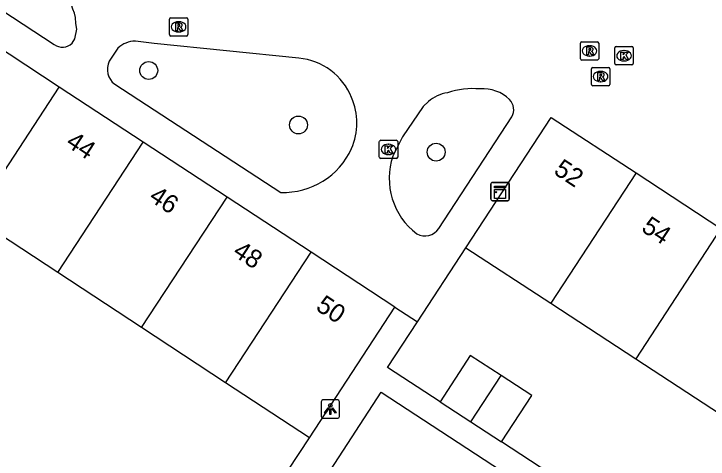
# Model space of a CAD drawing. Extents: x 159280 to 160375, y 384531 to 385872.
# Drawn here: x 159696.06 to 159733.94, y 384954.59 to 384978.88 of the extents above; entities that cross this region are included whole.
import ezdxf

# ---------------------------------------------------------------- set-up
doc = ezdxf.new("R2010")
doc.units = 0
for name, color, linetype in [('IMGEO_Boom', 7, 'Continuous'), ('IMGEO_Kast', 7, 'Continuous'), ('IMGEO_Kolk', 7, 'Continuous'), ('IMGEO_Lichtpunt', 7, 'Continuous'), ('IMGEO_Pand', 7, 'Continuous'), ('IMGEO_Pand_nummerreeks', 7, 'Continuous'), ('IMGEO_Rijbaan_lokaal_open', 7, 'Continuous'), ('IMGEO_Rioolput', 7, 'Continuous'), ('IMGEO_Voetpad_open', 7, 'Continuous')]:
    doc.layers.add(name, color=color, linetype=linetype)

msp = doc.modelspace()

# ---------------------------------------------------------------- linework, layer by layer
at = {"layer": 'IMGEO_Boom'}
for centre in [(159703.416, 384975.788), (159711.587, 384972.816), (159719.098, 384971.334)]:
    msp.add_circle(centre, 0.489, dxfattribs=at)
at = {"layer": 'IMGEO_Kast'}
for p, q in [((159722.091, 384968.761), (159722.091, 384969.602)), ((159722.091, 384969.602), (159722.091, 384968.761)), ((159722.166, 384969.686), (159723.007, 384969.686)), ((159723.007, 384969.686), (159722.166, 384969.686)), ((159723.091, 384969.611), (159723.091, 384968.77)), ((159723.091, 384968.77), (159723.091, 384969.611)), ((159723.016, 384968.686), (159722.175, 384968.686)), ((159722.175, 384968.686), (159723.016, 384968.686))]:
    msp.add_line(p, q, dxfattribs=at)
for points in [[(159722.286, 384969.476), (159722.886, 384969.476), (159722.886, 384969.391), (159722.286, 384969.391), (159722.286, 384969.476)], [(159722.286, 384969.301), (159722.886, 384969.301), (159722.886, 384968.812), (159722.286, 384968.812), (159722.286, 384969.301)]]:
    msp.add_lwpolyline(points, dxfattribs=at)
msp.add_circle((159722.37, 384969.15), 0.0377, dxfattribs=at)
for centre, start, end in [((159722.169, 384969.608), 92.4484, 184.2845), ((159722.169, 384969.608), 92.4484, 184.2845), ((159723.013, 384969.608), 2.4484, 94.2845), ((159723.013, 384969.608), 2.4484, 94.2845), ((159722.169, 384968.764), 182.4484, 274.2845), ((159722.169, 384968.764), 182.4484, 274.2845), ((159723.013, 384968.764), 272.4484, 4.2845), ((159723.013, 384968.764), 272.4484, 4.2845)]:
    msp.add_arc(centre, 0.0779, start, end, dxfattribs=at)
at = {"layer": 'IMGEO_Kolk'}
for p, q in [((159728.852, 384976.167), (159728.852, 384977.019)), ((159728.927, 384977.093), (159729.779, 384977.093)), ((159729.34, 384976.873), (159729.365, 384976.873)), ((159729.853, 384977.019), (159729.853, 384976.167)), ((159729.779, 384976.093), (159728.927, 384976.093)), ((159729.363, 384976.313), (159729.338, 384976.313)), ((159715.999, 384971.055), (159715.999, 384971.907)), ((159716.074, 384971.981), (159716.926, 384971.981)), ((159717, 384971.907), (159717, 384971.055)), ((159716.487, 384971.761), (159716.512, 384971.761)), ((159716.51, 384971.201), (159716.485, 384971.201)), ((159716.926, 384970.981), (159716.074, 384970.981))]:
    msp.add_line(p, q, dxfattribs=at)
for points in [[(159728.852, 384976.167), (159728.852, 384977.019)], [(159728.927, 384977.093), (159729.779, 384977.093)], [(159729.173, 384976.793), (159729.296, 384976.793), (159729.296, 384976.642), (159729.426, 384976.793), (159729.59, 384976.793), (159729.444, 384976.642), (159729.597, 384976.393), (159729.445, 384976.393), (159729.36, 384976.557), (159729.296, 384976.49), (159729.296, 384976.393), (159729.173, 384976.393), (159729.173, 384976.793)], [(159729.853, 384977.019), (159729.853, 384976.167)], [(159729.779, 384976.093), (159728.927, 384976.093)], [(159715.999, 384971.055), (159715.999, 384971.907)], [(159716.074, 384971.981), (159716.926, 384971.981)], [(159717, 384971.907), (159717, 384971.055)], [(159716.32, 384971.681), (159716.443, 384971.681), (159716.443, 384971.53), (159716.573, 384971.681), (159716.737, 384971.681), (159716.591, 384971.53), (159716.744, 384971.281), (159716.592, 384971.281), (159716.507, 384971.445), (159716.443, 384971.378), (159716.443, 384971.281), (159716.32, 384971.281), (159716.32, 384971.681)], [(159716.926, 384970.981), (159716.074, 384970.981)]]:
    msp.add_lwpolyline(points, dxfattribs=at)
for centre, start, end in [((159728.929, 384977.017), 91.552, 178.448), ((159728.929, 384977.017), 91.552, 178.448), ((159729.777, 384977.017), 1.552, 88.448), ((159729.777, 384977.017), 1.552, 88.448), ((159728.929, 384976.169), 181.552, 268.448), ((159728.929, 384976.169), 181.552, 268.448), ((159729.777, 384976.169), 271.552, 358.448), ((159729.777, 384976.169), 271.552, 358.448), ((159716.076, 384971.905), 91.552, 178.448), ((159716.076, 384971.905), 91.552, 178.448), ((159716.924, 384971.905), 1.552, 88.448), ((159716.924, 384971.905), 1.552, 88.448), ((159716.076, 384971.057), 181.552, 268.448), ((159716.076, 384971.057), 181.552, 268.448), ((159716.924, 384971.057), 271.552, 358.448), ((159716.924, 384971.057), 271.552, 358.448)]:
    msp.add_arc(centre, 0.0765, start, end, dxfattribs=at)
for centre, major_axis, ratio, start_param, end_param in [((159729.339, 384976.593), (-0.387, 0.002), 0.722429, 4.712389, 7.853982), ((159729.364, 384976.593), (-0.39, 0.002), 0.717154, 1.570796, 4.712389), ((159716.486, 384971.481), (-0.387, 0.002), 0.722429, 4.712389, 7.853982), ((159716.511, 384971.481), (-0.39, 0.002), 0.717154, 1.570796, 4.712389)]:
    msp.add_ellipse(centre, major_axis=major_axis, ratio=ratio, start_param=start_param, end_param=end_param, dxfattribs=at)
at = {"layer": 'IMGEO_Lichtpunt'}
for p, q in [((159713.73, 384957.814), (159712.922, 384957.814)), ((159713.73, 384957.814), (159712.922, 384957.814)), ((159712.828, 384957.719), (159712.828, 384956.912)), ((159712.828, 384957.719), (159712.828, 384956.912)), ((159713.824, 384956.912), (159713.824, 384957.719)), ((159713.824, 384956.912), (159713.824, 384957.719)), ((159712.922, 384956.818), (159713.73, 384956.818)), ((159712.922, 384956.818), (159713.73, 384956.818))]:
    msp.add_line(p, q, dxfattribs=at)
for points in [[(159713.202, 384957.383), (159713.241, 384957.355), (159713.053, 384957.093), (159713.015, 384957.12), (159713.202, 384957.383)], [(159713.304, 384957.335), (159713.351, 384957.335), (159713.351, 384957.013), (159713.304, 384957.013), (159713.304, 384957.335)], [(159713.414, 384957.355), (159713.452, 384957.382), (159713.639, 384957.12), (159713.6, 384957.092), (159713.414, 384957.355)]]:
    msp.add_lwpolyline(points, dxfattribs=at)
msp.add_circle((159713.327, 384957.517), 0.0994, dxfattribs=at)
for centre, start, end in [((159712.922, 384957.719), 90, 180), ((159712.922, 384957.719), 90, 180), ((159713.73, 384957.719), 0, 90), ((159713.73, 384957.719), 0, 90), ((159712.922, 384956.912), 180, 270), ((159712.922, 384956.912), 180, 270), ((159713.73, 384956.912), 270, 0), ((159713.73, 384956.912), 270, 360)]:
    msp.add_arc(centre, 0.0946, start, end, dxfattribs=at)
at = {"layer": 'IMGEO_Pand'}
for points in [[(159698.538, 384974.885), (159693.959, 384977.887)], [(159693.869, 384967.763), (159698.538, 384974.885)], [(159703.117, 384971.883), (159698.538, 384974.885)], [(159720.725, 384966.117), (159725.373, 384973.227), (159730.005, 384970.198)], [(159698.448, 384964.761), (159703.117, 384971.883)], [(159707.697, 384968.881), (159703.117, 384971.883)], [(159730.005, 384970.198), (159725.356, 384963.089)], [(159730.005, 384970.198), (159734.637, 384967.169)], [(159703.027, 384961.759), (159707.697, 384968.881)], [(159712.276, 384965.879), (159707.697, 384968.881)], [(159698.448, 384964.761), (159693.869, 384967.763)], [(159734.637, 384967.169), (159729.987, 384960.06)], [(159707.607, 384958.757), (159712.276, 384965.879)], [(159716.853, 384962.879), (159712.276, 384965.879)], [(159720.725, 384966.117), (159725.356, 384963.089)], [(159703.027, 384961.759), (159698.448, 384964.761)], [(159712.186, 384955.755), (159716.853, 384962.879)], [(159725.356, 384963.089), (159729.987, 384960.06)], [(159707.607, 384958.757), (159703.027, 384961.759)], [(159722.64, 384959.148), (159720.959, 384960.24), (159719.314, 384957.719)], [(159729.987, 384960.06), (159734.619, 384957.031)], [(159720.997, 384956.621), (159722.64, 384959.148)], [(159722.661, 384955.535), (159724.32, 384958.056), (159722.64, 384959.148)], [(159712.186, 384955.755), (159707.607, 384958.757)], [(159719.314, 384957.719), (159720.997, 384956.621)], [(159720.997, 384956.621), (159722.661, 384955.535)]]:
    msp.add_lwpolyline(points, dxfattribs=at)
at = {"layer": 'IMGEO_Rijbaan_lokaal_open'}
for points in [[(159692.009, 384981.311), (159698.26, 384977.213)], [(159699.235, 384977.28), (159699.377, 384977.512), (159699.488, 384978.044), (159699.445, 384978.349), (159699.414, 384978.679)], [(159711.609, 384976.462), (159703.716, 384977.269), (159702.686, 384977.391)], [(159701.732, 384977.01), (159701.259, 384976.294)], [(159701.56, 384975.036), (159710.618, 384969.135)], [(159718.677, 384974.088), (159718.395, 384973.82), (159717.26, 384972.167), (159716.74, 384971.117)], [(159719.249, 384967.174), (159723.228, 384973.261)], [(159718.079, 384962.075), (159720.725, 384966.117)], [(159716.853, 384962.879), (159718.079, 384962.075)]]:
    msp.add_lwpolyline(points, dxfattribs=at)
for centre, radius, start, end in [((159696.158, 384978.012), 3.324, 11.5838, 44.6111), ((159698.71, 384977.793), 0.734, 232.2097, 315.6525), ((159702.711, 384975.942), 1.449, 91.0084, 132.5323), ((159711.305, 384973.07), 3.406, 21.2987, 84.8784), ((159702.202, 384975.855), 1.04, 155.0109, 231.9013), ((159719.981, 384972.625), 1.96, 97.5774, 131.7225), ((159721.111, 384970.498), 4.3, 84.8983, 108.8255), ((159721.67, 384972.728), 2.061, 45.6703, 94.9278), ((159711.381, 384972.909), 3.398, 336.1645, 24.2904), ((159722.54, 384973.653), 0.792, 330.3634, 43.9316), ((159710.758, 384973.23), 4.098, 268.0431, 335.5757), ((159720.31, 384969.899), 3.772, 161.1552, 233.1396), ((159718.49, 384967.675), 0.909, 240.8167, 326.5819)]:
    msp.add_arc(centre, radius, start, end, dxfattribs=at)
at = {"layer": 'IMGEO_Rioolput'}
for p, q in [((159704.623, 384978.669), (159705.475, 384978.669)), ((159704.548, 384977.743), (159704.548, 384978.595)), ((159705.036, 384978.449), (159705.061, 384978.449)), ((159705.549, 384978.595), (159705.549, 384977.743)), ((159705.059, 384977.889), (159705.034, 384977.889)), ((159705.475, 384977.669), (159704.623, 384977.669)), ((159726.968, 384976.431), (159726.968, 384977.283)), ((159727.043, 384977.357), (159727.895, 384977.357)), ((159727.456, 384977.137), (159727.481, 384977.137)), ((159727.969, 384977.283), (159727.969, 384976.431)), ((159727.479, 384976.577), (159727.454, 384976.577)), ((159727.895, 384976.357), (159727.043, 384976.357)), ((159727.572, 384975.031), (159727.572, 384975.883)), ((159727.647, 384975.957), (159728.499, 384975.957)), ((159728.06, 384975.737), (159728.085, 384975.737)), ((159728.573, 384975.883), (159728.573, 384975.031)), ((159728.499, 384974.957), (159727.647, 384974.957)), ((159728.083, 384975.177), (159728.058, 384975.177))]:
    msp.add_line(p, q, dxfattribs=at)
for points in [[(159704.623, 384978.669), (159705.475, 384978.669)], [(159704.548, 384977.743), (159704.548, 384978.595)], [(159705.137, 384978.367), (159704.885, 384978.369), (159704.885, 384977.969)], [(159705.063, 384978.288), (159705.009, 384978.288), (159705.009, 384978.207)], [(159705.549, 384978.595), (159705.549, 384977.743)], [(159704.885, 384977.969), (159705.009, 384977.969), (159705.009, 384978.131), (159705.02, 384978.131)], [(159705.009, 384978.207), (159705.061, 384978.207)], [(159705.067, 384978.102), (159705.138, 384977.969), (159705.278, 384977.969), (159705.213, 384978.095)], [(159705.475, 384977.669), (159704.623, 384977.669)], [(159726.968, 384976.431), (159726.968, 384977.283)], [(159727.043, 384977.357), (159727.895, 384977.357)], [(159727.969, 384977.283), (159727.969, 384976.431)], [(159727.557, 384977.055), (159727.305, 384977.057), (159727.305, 384976.657)], [(159727.305, 384976.657), (159727.429, 384976.657), (159727.429, 384976.819), (159727.44, 384976.819)], [(159727.483, 384976.976), (159727.429, 384976.976), (159727.429, 384976.895)], [(159727.429, 384976.895), (159727.481, 384976.895)], [(159727.487, 384976.79), (159727.558, 384976.657), (159727.698, 384976.657), (159727.633, 384976.783)], [(159727.895, 384976.357), (159727.043, 384976.357)], [(159727.572, 384975.031), (159727.572, 384975.883)], [(159727.647, 384975.957), (159728.499, 384975.957)], [(159728.161, 384975.655), (159727.909, 384975.657), (159727.909, 384975.257)], [(159728.573, 384975.883), (159728.573, 384975.031)], [(159727.909, 384975.257), (159728.033, 384975.257), (159728.033, 384975.419), (159728.044, 384975.419)], [(159728.087, 384975.576), (159728.033, 384975.576), (159728.033, 384975.495)], [(159728.033, 384975.495), (159728.085, 384975.495)], [(159728.091, 384975.39), (159728.162, 384975.257), (159728.302, 384975.257), (159728.237, 384975.383)], [(159728.499, 384974.957), (159727.647, 384974.957)]]:
    msp.add_lwpolyline(points, dxfattribs=at)
for centre, radius, start, end in [((159704.625, 384978.593), 0.0765, 91.552, 178.448), ((159704.625, 384978.593), 0.0765, 91.552, 178.448), ((159705.473, 384978.593), 0.0765, 1.552, 88.448), ((159705.473, 384978.593), 0.0765, 1.552, 88.448), ((159705.069, 384978.192), 0.0964, 77.0061, 93.1865), ((159705.083, 384978.249), 0.0378, 276.6634, 79.6772), ((159705.136, 384978.257), 0.109, 350.3612, 89.416), ((159705.019, 384978.078), 0.0533, 26.0293, 88.6989), ((159705.045, 384978.396), 0.19, 274.7715, 282.9687), ((159705.134, 384978.257), 0.112, 277.5842, 350.9817), ((159705.118, 384978.042), 0.108, 29.5134, 73.7905), ((159704.625, 384977.745), 0.0765, 181.552, 268.448), ((159704.625, 384977.745), 0.0765, 181.552, 268.448), ((159705.473, 384977.745), 0.0765, 271.552, 358.448), ((159705.473, 384977.745), 0.0765, 271.552, 358.448), ((159727.045, 384977.281), 0.0765, 91.552, 178.448), ((159727.045, 384977.281), 0.0765, 91.552, 178.448), ((159727.893, 384977.281), 0.0765, 1.552, 88.448), ((159727.893, 384977.281), 0.0765, 1.552, 88.448), ((159727.439, 384976.766), 0.0533, 26.0293, 88.6989), ((159727.465, 384977.084), 0.19, 274.7715, 282.9687), ((159727.489, 384976.88), 0.0964, 77.0061, 93.1865), ((159727.503, 384976.937), 0.0378, 276.6634, 79.6772), ((159727.556, 384976.945), 0.109, 350.3612, 89.416), ((159727.554, 384976.945), 0.112, 277.5842, 350.9817), ((159727.538, 384976.73), 0.108, 29.5134, 73.7905), ((159727.045, 384976.433), 0.0765, 181.552, 268.448), ((159727.045, 384976.433), 0.0765, 181.552, 268.448), ((159727.893, 384976.433), 0.0765, 271.552, 358.448), ((159727.893, 384976.433), 0.0765, 271.552, 358.448), ((159727.649, 384975.881), 0.0765, 91.552, 178.448), ((159727.649, 384975.881), 0.0765, 91.552, 178.448), ((159728.16, 384975.545), 0.109, 350.3612, 89.416), ((159728.497, 384975.881), 0.0765, 1.552, 88.448), ((159728.497, 384975.881), 0.0765, 1.552, 88.448), ((159728.043, 384975.366), 0.0533, 26.0293, 88.6989), ((159728.069, 384975.684), 0.19, 274.7715, 282.9687), ((159728.093, 384975.48), 0.0964, 77.0061, 93.1865), ((159728.107, 384975.537), 0.0378, 276.6634, 79.6772), ((159728.158, 384975.545), 0.112, 277.5842, 350.9817), ((159728.142, 384975.33), 0.108, 29.5134, 73.7905), ((159727.649, 384975.033), 0.0765, 181.552, 268.448), ((159727.649, 384975.033), 0.0765, 181.552, 268.448), ((159728.497, 384975.033), 0.0765, 271.552, 358.448), ((159728.497, 384975.033), 0.0765, 271.552, 358.448)]:
    msp.add_arc(centre, radius, start, end, dxfattribs=at)
for centre, major_axis, ratio, start_param, end_param in [((159705.035, 384978.169), (-0.387, 0.002), 0.722429, 4.712389, 7.853982), ((159705.06, 384978.169), (-0.39, 0.002), 0.717154, 1.570796, 4.712389), ((159727.455, 384976.857), (-0.387, 0.002), 0.722429, 4.712389, 7.853982), ((159727.48, 384976.857), (-0.39, 0.002), 0.717154, 1.570796, 4.712389), ((159728.059, 384975.457), (-0.387, 0.002), 0.722429, 4.712389, 7.853982), ((159728.084, 384975.457), (-0.39, 0.002), 0.717154, 1.570796, 4.712389)]:
    msp.add_ellipse(centre, major_axis=major_axis, ratio=ratio, start_param=start_param, end_param=end_param, dxfattribs=at)
at = {"layer": 'IMGEO_Voetpad_open'}
for points in [[(159719.314, 384957.719), (159716.45, 384959.588), (159718.079, 384962.075)], [(159713.342, 384953.983), (159716.103, 384958.24), (159734.316, 384946.329), (159731.479, 384942.017)], [(159702.6, 384947.788), (159705.624, 384945.802), (159712.186, 384955.755)], [(159728.517, 384951.699), (159722.661, 384955.535)]]:
    msp.add_lwpolyline(points, dxfattribs=at)

# ---------------------------------------------------------------- texts
at = {"layer": 'IMGEO_Pand_nummerreeks'}
for s, rotation, p in [('44', 326.5565, (159698.834, 384971.705)), ('52', 326.6195, (159725.456, 384970.189)), ('46', 326.5565, (159703.371, 384968.731)), ('54', 326.6195, (159730.237, 384967.062)), ('48', 326.5565, (159707.944, 384965.733)), ('50', 326.5565, (159712.477, 384962.761))]:
    msp.add_text(s, height=1, rotation=rotation, dxfattribs=at).set_placement(p)

doc.saveas('drawing.dxf')
